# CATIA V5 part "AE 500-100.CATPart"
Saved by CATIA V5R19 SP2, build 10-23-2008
Part number: AE 500-100
Bounding box of the stored display mesh (mm): x -22.494 to 22.494, y -22.494 to 22.494, z 0 to 250
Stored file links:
  C:\Users\Bora\Desktop\3D Katı model\AE serisi\AE 500\AE 500-100.CATPart
  C:\Program Files\Dassault Systemes\B19\intel_a\reffiles\standard\MetricThickPitch.txt
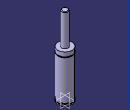
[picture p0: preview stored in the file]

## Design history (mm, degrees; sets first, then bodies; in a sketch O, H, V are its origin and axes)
Body1 (main body)
  Sketch1 on yz-plane, origin (0, 0, 0), H (0, 1, 0), V (0, 0, 1)
    point P1 (22.5, 133.5)
    point P8 (22.5, 135.5)
    point P9 (22.5, 135.5)
    point P10 (22.5, 133.5)
    point P11 (10, 248)
    point P13 (10, 248)
    line L1 (22.5, 133.5) -> (22.5, 8)
    line L2 (22.5, 4) -> (22.5, 0)
    line L3 (20, 8) -> (20, 4)
    line L4 (22.5, 149) -> (22.5, 135.5)
    arc A1 centre (22.5, 134.5) radius 1 from (22.5, 135.5) to (22.5, 133.5) ccw
    line L5 (10, 248) -> (10, 149)
    arc A2 centre (8, 248) radius 2 from (10, 248) to (8, 250) ccw
    line L6 (8, 250) -> (0, 250)
    point P15 (0, 250)
    line L7 (10, 149) -> (22.5, 149)
    line L8 (0, 0) -> (22.5, 0)
    line L9 (20, 8) -> (22.5, 8)
    line L10 (20, 4) -> (22.5, 4)
    coincidence: P15 V, P1 P10, P8 P9, P11 P13
    tangency: L6 A2
    horizontal: L7 H, L8 H, L9 H, L10 H
  Shaft1: profile Sketch1, axis Sketch1.V, angle 360
  Sketch2 on face of Shaft1 from Sketch1.L8, origin (0, 0, 0), H (1, 0, 0), V (0, -1, 0)
    point P1 (10, 0)
    distance P1 V = 10
  Hole1: placed by Sketch2, at (10, 0, 0) direction (0, 0, 1), diameter 6.647, depth 13, threaded "M8", thread diameter 8, thread depth 13, pitch 1.25
  CircPattern1: of Hole1, instances 2, angular step 180, axis from xy-plane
